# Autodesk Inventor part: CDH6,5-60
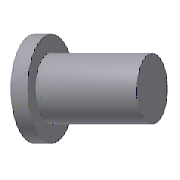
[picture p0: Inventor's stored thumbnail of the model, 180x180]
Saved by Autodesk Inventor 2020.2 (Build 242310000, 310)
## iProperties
Manager: www.cadconsulting.pl
Company: Fabian Stasiak CAD Consulting
Created: 2014-02
Part Number: CDH6,5-60
Material: SKD61
Description: Straight Core Pin
Document SubType Name: Modeling
Designer: F.Stasiak
Standard Revision: 1
Manufacturer: PUNCH
Language: pl-PL
Size Designation: 6,5-60
Categories: <MemberInstance><Categories><Category DisplayName="Forma wtryskowa" InternalName="349578f2-f4d4-4954-8c09-8e99297a61c0" Mnemonic="MOLD"><Category DisplayName="W
Mass: 1.61494 g
Surface Area: 11.4822 cm^2
Volume: 1.61494 cm^3
Density: 7.8 g/cm^3
Appearance: Aluminium - ciemne
Catalog Web Link: www.expertbooks.pl
IsCustomPart: 1
Author: F.Stasiak
Subject: Zbiór ćwiczeń. Autodesk Inventor 2020. Kurs Professional
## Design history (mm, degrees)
sketch "Sketch1"
  geometry: L1 (5, 0)-(5, 4); L2 (5, 4)-(3.25, 4); L3 (3.25, 4)-(3.25, 60); L4 (3.25, 60)-(0, 60); L5 (5, 0)-(0, 0); L6 (0, 0)-(0, 60); L7 (0, 60)-(0, -10) reference; 1 further point
  constraints: 14 end point, 2 horizontal, 1 coincident, 1 collinear, 1 parallel
  dimensions: "d2" = 4 distance of L1.start L1.end (= T_); "d19" = 60 distance between parallel lines of L4 L5 (= L); "d38" = 6.5 diameter of L3 L7 (= P); "d39" = 10 diameter of L1 L7 (= H_)
revolve "Revolution1" sketch "Sketch1" stored, may be unused: angle "d4" = 90 deg
fillet "Fillet1" dims "d36" = 0.3
workplane "Work Plane1"
sketch "Sketch2"
  geometry: 2 further points
  constraints: 1 vertical alignment
  dimensions: "d21" = 2 distance of point (0, -2) point (0, 0) (= 0.5 x T_)
hole "Anti_Rotary Hole" sketch "Sketch2" at (0, 0) diameter "d22" = 0.8 (= Anti_Rotary_D); stored, may be unused: countersink angle "d26" = 90 deg, drill point angle "d28" = 118 deg; dims "d23" = 6, "d24" = 4, "d25" = 2, "d27" = 1.2 (= 1.5 x Anti_Rotary_D)
sketch "Sketch3"
  geometry: L1 (-3.55, 3.521)-(-3.55, -3.521); A1 r 5 centre (0, 0) between (-3.55, 3.521) and (-3.55, -3.521) reference; 1 further point
  constraints: 2 end point, 2 point on circle, 1 vertical
  dimensions: "d29" = 3.55 distance from line of point (0, 0) L1 (= Anti_Rotary_P)
extrude "Anti_Rotary Plane" cut sketch "Sketch3" extent not by distance; stored distance "d30" = 10; taper "d31" = 0 deg
body "Solid1"
other parameters: "H_" = 10 [user parameter; used in 1 equation term], "L" = 60 [user parameter; used in 1 equation term], "P" = 6.5 [user parameter; used in 1 equation term], "d7" = 0, "d8" = 0, "T_" = 4 [user parameter; used in 2 equation terms], "Anti_Rotary_P" = 3.55 [user parameter; used in 1 equation term], "Anti_Rotary_D" = 0.8 [user parameter; used in 2 equation terms], "d32" = 0, "d33" = 0, "d34" = 0, "d35" = 0, "IsARPlane" = 0 [user parameter], "IsARHole" = 0 [user parameter]
